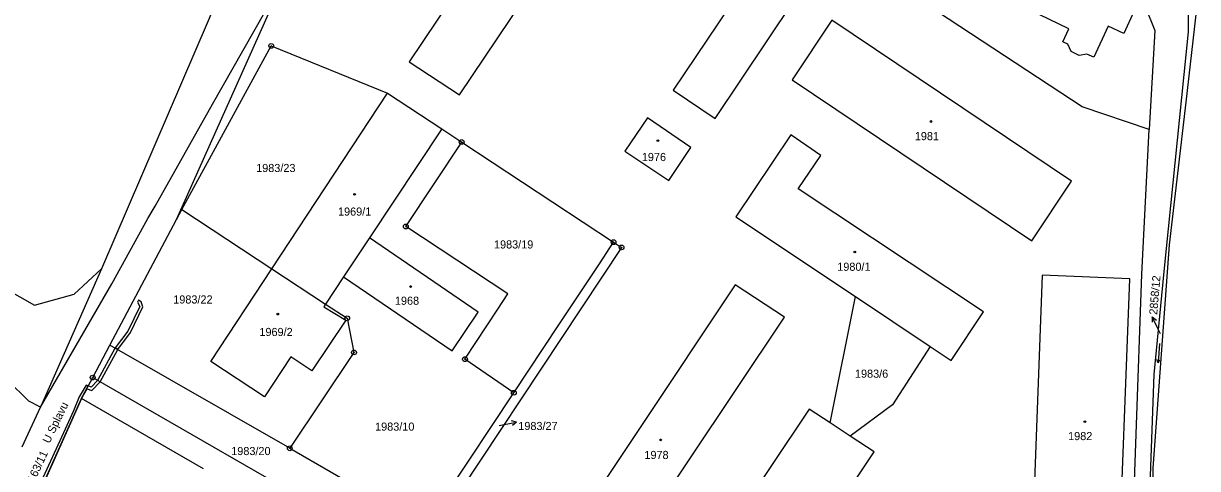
# Model space of a CAD drawing. Extents: x -562167 to -556918, y -1077891 to -1070763.
# Drawn here: x -560397.3 to -560151.9, y -1077121.5 to -1077028.4 of the extents above; entities that cross this region are included whole.
import ezdxf

# ---------------------------------------------------------------- set-up
doc = ezdxf.new("R2010")
doc.units = 0
for name, color, linetype in [('Hranice parcel', 7, 'Continuous'), ('Parcelní čísla', 7, 'Continuous'), ('Pop  PČ popisy', 7, 'Continuous'), ('Věcná břemena k části', 7, 'Continuous'), ('Značky bodu BP', 7, 'Continuous'), ('Značky budov', 7, 'Continuous'), ('Značky kultur', 7, 'Continuous')]:
    doc.layers.add(name, color=color, linetype=linetype)

msp = doc.modelspace()

# ---------------------------------------------------------------- linework, layer by layer
at = {"layer": 'Hranice parcel'}
for p, q in [((-560365.26, -1077069.4), (-560342.5, -1077018.31)), ((-560345.32, -1077079.71), (-560321.16, -1077042.96)), ((-560321.16, -1077042.96), (-560309.84, -1077050.42)), ((-560309.84, -1077050.42), (-560324.9, -1077073.21)), ((-560309.84, -1077050.42), (-560305.66, -1077053.18)), ((-560305.66, -1077053.18), (-560273.91, -1077074.13)), ((-560365.26, -1077069.4), (-560364.13, -1077067.33)), ((-560364.13, -1077067.33), (-560345.32, -1077079.71)), ((-560379.17, -1077095.66), (-560365.26, -1077069.4)), ((-560324.9, -1077073.21), (-560330.37, -1077081.4)), ((-560161.15, -1077121.46), (-560157.7, -1077074.67)), ((-560380.96, -1077079.72), (-560393.7, -1077108.68)), ((-560345.32, -1077079.71), (-560334.11, -1077087.09)), ((-560330.37, -1077081.4), (-560334.11, -1077087.09)), ((-560228.64, -1077111.96), (-560223.33, -1077085.54)), ((-560223.33, -1077085.54), (-560207.75, -1077095.95)), ((-560382.79, -1077102.48), (-560379.17, -1077095.66)), ((-560341.6, -1077117.28), (-560379.17, -1077095.66)), ((-560385.1, -1077106.84), (-560382.79, -1077102.48)), ((-560385.1, -1077106.84), (-560400.84, -1077142.03)), ((-560359.62, -1077121.58), (-560385.1, -1077106.84)), ((-560313.25, -1077133.6), (-560294.76, -1077105.65)), ((-560397.56, -1077116.96), (-560393.7, -1077108.68)), ((-560224.47, -1077114.71), (-560228.64, -1077111.96)), ((-560341.6, -1077117.28), (-560323.85, -1077127.49)), ((-560160.99, -1077155.03), (-560161.15, -1077121.46))]:
    msp.add_line(p, q, dxfattribs=at)
for points in [[(-560253.06, -1076964.3), (-560263.6, -1076957.2), (-560267.57, -1076963.12), (-560268.82, -1076962.29), (-560270.82, -1076965.28), (-560269.58, -1076966.11), (-560284.86, -1076988.9), (-560286.16, -1076988.02), (-560288.15, -1076991.05), (-560286.85, -1076991.87), (-560316.67, -1077036.36), (-560306.13, -1077043.3), (-560290.21, -1077019.59), (-560286.77, -1077021.96), (-560253.61, -1076972.43), (-560257, -1076970.16), (-560253.06, -1076964.3)], [(-560219.92, -1076999.22), (-560228.6, -1076993.37), (-560261.43, -1077042.32), (-560252.66, -1077048.23), (-560219.92, -1076999.22)], [(-560187.28, -1076993.4), (-560183.21, -1076995.5), (-560180.06, -1076997.25), (-560177.46, -1076999.96), (-560164.79, -1077019.71), (-560160.81, -1077029.84), (-560161.95, -1077050.53)], [(-560161.95, -1077050.53), (-560175.96, -1077045.8), (-560210.86, -1077022.78), (-560199.79, -1077004.72)], [(-560165.09, -1077025.71), (-560167.28, -1077030.45), (-560170.57, -1077028.95), (-560173.53, -1077035.43), (-560175, -1077034.76), (-560176.62, -1077035.08), (-560178.24, -1077034.22), (-560178.94, -1077032.72), (-560180.04, -1077032.21), (-560178.79, -1077029.48), (-560184.98, -1077026.51), (-560178.57, -1077012.84), (-560165.96, -1077018.79), (-560168.41, -1077024.19), (-560165.09, -1077025.71)], [(-560393.7, -1077108.68), (-560378.79, -1077082.83), (-560371.26, -1077069.21), (-560369.73, -1077066.57), (-560357.74, -1077045.23), (-560342.5, -1077018.31)], [(-560356.38, -1077022.25), (-560358.68, -1077027.79), (-560380.96, -1077079.72)], [(-560160.99, -1077155.03), (-560161.61, -1077141.5), (-560161.97, -1077130.79), (-560160.9, -1077101.8), (-560158.8, -1077080.3), (-560153.74, -1077030.09), (-560153.76, -1077022.75)], [(-560157.7, -1077074.67), (-560154.26, -1077044.8), (-560151.86, -1077024.03)], [(-560178.19, -1077061.35), (-560228.3, -1077027.65), (-560236.61, -1077040.16), (-560186.49, -1077073.87), (-560178.19, -1077061.35)], [(-560497.46, -1077029.04), (-560394.94, -1077087.31), (-560386.68, -1077085.02), (-560380.96, -1077079.72)], [(-560364.13, -1077067.33), (-560345.47, -1077033.05), (-560321.16, -1077042.96)], [(-560257.75, -1077054.32), (-560266.85, -1077048.13), (-560271.54, -1077055.11), (-560262.34, -1077061.21), (-560257.75, -1077054.32)], [(-560165.84, -1077157.89), (-560165.84, -1077147.82), (-560163.5, -1077080.8), (-560161.95, -1077050.53)], [(-560207.75, -1077095.95), (-560203.38, -1077098.87), (-560196.56, -1077088.72), (-560235.3, -1077062.99), (-560230.58, -1077055.99), (-560236.86, -1077051.66), (-560248.38, -1077068.8), (-560223.33, -1077085.54)], [(-560294.76, -1077105.65), (-560304.97, -1077098.63), (-560298.13, -1077088.17), (-560296.02, -1077084.94), (-560317.34, -1077070.86), (-560305.66, -1077053.18)], [(-560330.37, -1077081.4), (-560307.66, -1077096.85), (-560302.21, -1077088.8), (-560324.9, -1077073.21)], [(-560273.91, -1077074.13), (-560272.24, -1077075.23), (-560318.45, -1077145.05)], [(-560294.76, -1077105.65), (-560285.52, -1077091.68), (-560276.89, -1077078.64), (-560273.91, -1077074.13)], [(-560334.11, -1077087.09), (-560334.48, -1077087.65), (-560329.85, -1077090.48), (-560336.97, -1077101.08), (-560341.4, -1077098.16), (-560346.89, -1077106.49), (-560358.09, -1077099.13), (-560345.32, -1077079.71)], [(-560165.98, -1077081.83), (-560184.3, -1077081.05), (-560186.7, -1077144.83), (-560168.43, -1077145.6), (-560165.98, -1077081.83)], [(-560238.22, -1077089.84), (-560248.49, -1077083.07), (-560288.52, -1077143.22), (-560278.34, -1077149.95), (-560238.22, -1077089.84)], [(-560334.11, -1077087.09), (-560329.58, -1077090.07), (-560328.17, -1077097.21), (-560341.6, -1077117.28)], [(-560393.7, -1077108.68), (-560396.15, -1077107.42), (-560400.64, -1077102.93), (-560411.2, -1077096.49)], [(-560207.75, -1077095.95), (-560215.59, -1077108.15), (-560224.47, -1077114.71)], [(-560382.79, -1077102.48), (-560328.09, -1077133.97), (-560323.85, -1077127.49)], [(-560228.64, -1077111.96), (-560233, -1077109.08), (-560257.19, -1077145.32), (-560251.24, -1077149.27), (-560252.04, -1077150.47), (-560250.48, -1077151.5), (-560249.68, -1077150.31), (-560244.02, -1077154.07), (-560246.98, -1077158.54), (-560243.2, -1077161.05), (-560236.88, -1077151.77), (-560240.4, -1077149.42), (-560219.46, -1077118.02), (-560224.47, -1077114.71)]]:
    msp.add_lwpolyline(points, dxfattribs=at)
at = {"layer": 'Pop  PČ popisy'}
for p, q in [((-560161.31, -1077089.77), (-560161.32, -1077090.89)), ((-560159.99, -1077092.47), (-560161.31, -1077089.77)), ((-560161.31, -1077089.77), (-560160.42, -1077090.45)), ((-560159.58, -1077093.3), (-560159.99, -1077092.47)), ((-560297.13, -1077112.39), (-560294.18, -1077111.82)), ((-560294.18, -1077111.82), (-560295.26, -1077111.52)), ((-560294.18, -1077111.82), (-560295.07, -1077112.5)), ((-560297.86, -1077112.53), (-560297.13, -1077112.39))]:
    msp.add_line(p, q, dxfattribs=at)
at = {"layer": 'Věcná břemena k části'}
for points in [[(-560375.43, -1077092.73), (-560378.12, -1077096.26), (-560377.55, -1077096.59), (-560374.91, -1077093.04), (-560372.28, -1077087.65), (-560372.64, -1077086.61), (-560373.19, -1077086.31), (-560373.41, -1077086.72), (-560372.93, -1077087.61)], [(-560385.1, -1077106.84), (-560383.91, -1077104.8), (-560382.98, -1077105.21), (-560381.21, -1077103.39), (-560377.55, -1077096.59), (-560378.12, -1077096.26), (-560381.75, -1077103.08), (-560383.12, -1077104.49), (-560383.72, -1077104.23)]]:
    msp.add_lwpolyline(points, close=True, dxfattribs=at)
msp.add_lwpolyline([(-560399.46, -1077138.95), (-560385.1, -1077106.84), (-560383.72, -1077104.23), (-560384.16, -1077104.04), (-560385.61, -1077106.49), (-560386.81, -1077109.43), (-560388.88, -1077114.07), (-560393.54, -1077124.22), (-560395.62, -1077128.99), (-560399.85, -1077138.41)], dxfattribs=at)
at = {"layer": 'Značky bodu BP'}
for centre, radius in [((-560345.47, -1077033.05), 0.5), ((-560345.47, -1077033.05), 0.0303), ((-560305.66, -1077053.18), 0.5), ((-560305.66, -1077053.18), 0.0303), ((-560317.34, -1077070.86), 0.5), ((-560317.34, -1077070.86), 0.0303), ((-560273.91, -1077074.13), 0.5), ((-560273.91, -1077074.13), 0.0303), ((-560272.24, -1077075.23), 0.5), ((-560272.24, -1077075.23), 0.0303), ((-560329.58, -1077090.07), 0.5), ((-560329.58, -1077090.07), 0.0303), ((-560328.17, -1077097.21), 0.5), ((-560328.17, -1077097.21), 0.0303), ((-560304.97, -1077098.63), 0.5), ((-560304.97, -1077098.63), 0.0303), ((-560382.79, -1077102.48), 0.5), ((-560382.79, -1077102.48), 0.0303), ((-560294.76, -1077105.65), 0.5), ((-560294.76, -1077105.65), 0.0303), ((-560341.6, -1077117.28), 0.5), ((-560341.6, -1077117.28), 0.0303)]:
    msp.add_circle(centre, radius, dxfattribs=at)
at = {"layer": 'Značky budov'}
for centre in [(-560207.57, -1077048.88), (-560264.65, -1077052.88), (-560328.05, -1077064.13), (-560223.49, -1077076.19), (-560316.33, -1077083.43), (-560344.1, -1077089.19), (-560175.4, -1077111.7), (-560264.06, -1077115.52)]:
    msp.add_circle(centre, 0.175, dxfattribs=at)
at = {"layer": 'Značky kultur'}
for p, q in [((-560159.81, -1077095.36), (-560160.09, -1077099.37)), ((-560160.09, -1077099.37), (-560160.38, -1077098.69)), ((-560160.09, -1077099.37), (-560159.71, -1077098.74))]:
    msp.add_line(p, q, dxfattribs=at)

# ---------------------------------------------------------------- texts
at = {"layer": 'Parcelní čísla'}
for s, p in [('1981', (-560210.95, -1077052.79)), ('1976', (-560268.01, -1077057.16)), ('1983/23', (-560348.62, -1077059.46)), ('1969/1', (-560331.51, -1077068.58)), ('1983/19', (-560298.91, -1077075.46)), ('1980/1', (-560227.16, -1077080.13)), ('1983/22', (-560365.95, -1077086.98)), ('1968', (-560319.62, -1077087.24)), ('1969/2', (-560347.94, -1077093.78)), ('1983/6', (-560223.46, -1077102.51)), ('1983/10', (-560323.76, -1077113.59)), ('1983/27', (-560293.83, -1077113.46)), ('1982', (-560178.91, -1077115.57)), ('1983/20', (-560353.83, -1077118.7)), ('1978', (-560267.47, -1077119.52))]:
    msp.add_text(s, height=1.7, dxfattribs=at).set_placement(p)
for s, rotation, p in [('2858/12', 85, (-560160.3, -1077089.39)), ('2163/11', 65, (-560395.56, -1077125.72))]:
    msp.add_text(s, height=1.7, rotation=rotation, dxfattribs=at).set_placement(p)
at = {"layer": 'Pop  PČ popisy'}
msp.add_text('U Splavu', height=1.7, rotation=64, dxfattribs=at).set_placement((-560391.84, -1077116.4))

doc.saveas('drawing.dxf')
